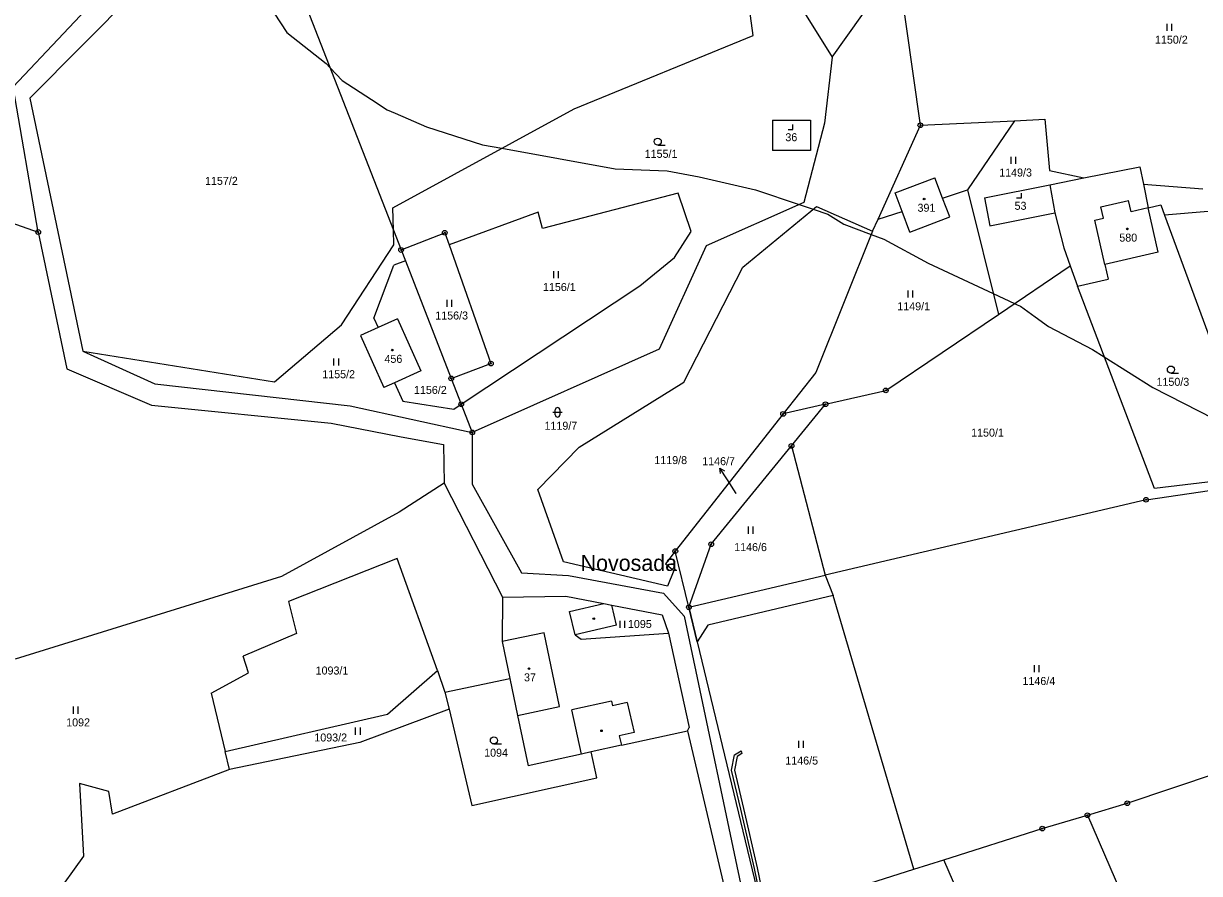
# Model space of a CAD drawing. Extents: x -439246 to -433691, y -1130252 to -1121148.
# Drawn here: x -438261.6 to -438011.8, y -1123663.3 to -1123482.7 of the extents above; entities that cross this region are included whole.
import ezdxf

# ---------------------------------------------------------------- set-up
doc = ezdxf.new("R2010")
doc.units = 0
for name, color, linetype in [('Vrstva 1', 7, 'Continuous'), ('Vrstva 16', 7, 'Continuous'), ('Vrstva 18', 7, 'Continuous'), ('Vrstva 19', 7, 'Continuous'), ('Vrstva 24', 7, 'Continuous'), ('Vrstva 25', 7, 'Continuous'), ('Vrstva 3', 7, 'Continuous'), ('Vrstva 30', 7, 'Continuous'), ('Vrstva 37', 7, 'Continuous'), ('Vrstva 4', 7, 'Continuous'), ('Vrstva 52', 7, 'Continuous'), ('Vrstva 62', 7, 'Continuous')]:
    doc.layers.add(name, color=color, linetype=linetype)

msp = doc.modelspace()

# ---------------------------------------------------------------- linework, layer by layer
at = {"layer": 'Vrstva 1'}
for p, q in [((-438023.75, -1123516.88), (-438011.16, -1123517.82)), ((-438009.98, -1123522.62), (-438019.24, -1123523.41)), ((-438091.26, -1123563.61), (-438078.47, -1123560.67)), ((-438091.26, -1123563.61), (-438100.25, -1123565.67)), ((-438098.48, -1123572.45), (-438091.26, -1123563.61)), ((-438120.28, -1123606.72), (-438091.32, -1123599.91)), ((-438089.62, -1123604.25), (-438116.28, -1123610.51)), ((-438072.52, -1123662.39), (-438089.62, -1123604.25)), ((-438116.28, -1123610.51), (-438118.5, -1123614.1)), ((-438104.43, -1123672.49), (-438072.52, -1123662.39)), ((-438072.52, -1123662.39), (-438066.16, -1123660.38))]:
    msp.add_line(p, q, dxfattribs=at)
for points in [[(-438106.64, -1123485.23), (-438113.81, -1123431.93)], [(-438206.8, -1123465.62), (-438183.03, -1123526.6)], [(-438103.03, -1123468.71), (-438089.87, -1123489.86)], [(-438089.87, -1123489.86), (-438077.24, -1123472.06)], [(-438071.12, -1123504.34), (-438075.63, -1123472.29)], [(-438263.78, -1123496.2), (-438242.36, -1123473.42)], [(-438237.94, -1123476.04), (-438260.21, -1123498.55)], [(-438144.62, -1123500.82), (-438106.64, -1123485.23)], [(-438089.87, -1123489.86), (-438091.5, -1123503.89)], [(-438258.45, -1123527.01), (-438263.78, -1123496.2)], [(-438260.21, -1123498.55), (-438248.99, -1123552.36)], [(-438183.13, -1123521.84), (-438144.62, -1123500.82)], [(-438102.52, -1123503.27), (-438094.42, -1123503.27)], [(-438102.52, -1123503.27), (-438102.52, -1123509.66)], [(-438091.5, -1123503.89), (-438095.89, -1123520.72)], [(-438094.42, -1123503.27), (-438094.42, -1123509.66)], [(-438080.11, -1123524.29), (-438071.12, -1123504.34)], [(-438071.12, -1123504.34), (-438051.14, -1123503.36)], [(-438051.14, -1123503.36), (-438061.1, -1123518.07)], [(-438051.14, -1123503.36), (-438044.71, -1123503.04)], [(-438044.71, -1123503.04), (-438043.71, -1123513.94)], [(-438094.42, -1123509.66), (-438102.52, -1123509.66)], [(-438043.71, -1123513.94), (-438036.4, -1123515.52)], [(-438036.4, -1123515.52), (-438024.49, -1123513.13)], [(-438024.49, -1123513.13), (-438023.75, -1123516.88)], [(-438285.12, -1123517.59), (-438258.45, -1123527.01)], [(-438057.46, -1123519.73), (-438043.63, -1123516.96)], [(-438043.63, -1123516.96), (-438036.4, -1123515.52)], [(-438043.63, -1123516.96), (-438042.54, -1123522.94)], [(-438023.75, -1123516.88), (-438022.76, -1123521.88)], [(-438122.56, -1123518.73), (-438151.35, -1123526.28)], [(-438119.76, -1123526.89), (-438122.56, -1123518.73)], [(-438066.38, -1123519.8), (-438061.1, -1123518.07)], [(-438064.85, -1123523.8), (-438066.38, -1123519.8)], [(-438061.1, -1123518.07), (-438054.54, -1123544.53)], [(-438057.46, -1123519.73), (-438056.37, -1123525.71)], [(-438183.03, -1123526.6), (-438183.13, -1123521.84)], [(-438095.89, -1123520.72), (-438116.59, -1123529.95)], [(-438108.81, -1123534.47), (-438093.2, -1123521.6)], [(-438093.2, -1123521.6), (-438081.26, -1123526.84)], [(-438080.11, -1123524.29), (-438075, -1123522.62)], [(-438073.32, -1123527.03), (-438075, -1123522.62)], [(-438022.76, -1123521.88), (-438020.04, -1123521.24)], [(-438020.62, -1123531.32), (-438022.76, -1123521.88)], [(-438020.04, -1123521.24), (-438019.24, -1123523.41)], [(-438152.25, -1123522.82), (-438171.21, -1123529.74)], [(-438151.35, -1123526.28), (-438152.25, -1123522.82)], [(-438081.26, -1123526.84), (-438080.11, -1123524.29)], [(-438073.32, -1123527.03), (-438064.85, -1123523.8)], [(-438056.37, -1123525.71), (-438042.54, -1123522.94)], [(-438042.54, -1123522.94), (-438040.62, -1123530.4)], [(-438019.24, -1123523.41), (-437998.91, -1123578.78)], [(-438258.45, -1123527.01), (-438252.37, -1123556.05)], [(-438182.96, -1123529.75), (-438183.03, -1123526.6)], [(-438183.03, -1123526.6), (-438181.38, -1123530.83)], [(-438181.38, -1123530.83), (-438172.12, -1123527.16)], [(-438172.12, -1123527.16), (-438171.21, -1123529.74)], [(-438123.35, -1123532.43), (-438119.76, -1123526.89)], [(-438081.26, -1123526.84), (-438093.3, -1123556.83)], [(-438194.05, -1123546.73), (-438182.96, -1123529.75)], [(-438171.21, -1123529.74), (-438162.31, -1123554.96)], [(-438116.59, -1123529.95), (-438126.59, -1123551.88)], [(-438181.38, -1123530.83), (-438180.48, -1123533.13)], [(-438130.67, -1123538.46), (-438123.35, -1123532.43)], [(-438040.62, -1123530.4), (-438039.27, -1123534.23)], [(-438020.62, -1123531.32), (-438031.93, -1123533.89)], [(-438187.18, -1123545.29), (-438182.94, -1123534.02)], [(-438180.48, -1123533.13), (-438182.94, -1123534.02)], [(-438180.48, -1123533.13), (-438170.74, -1123558.13)], [(-438121.32, -1123558.91), (-438108.81, -1123534.47)], [(-438054.54, -1123544.53), (-438039.27, -1123534.23)], [(-438039.27, -1123534.23), (-438037.75, -1123538.54)], [(-438031.93, -1123533.89), (-438031.21, -1123537.05)], [(-438037.75, -1123538.54), (-438031.21, -1123537.05)], [(-438168.6, -1123563.61), (-438130.67, -1123538.46)], [(-438021.41, -1123581.48), (-438037.75, -1123538.54)], [(-438078.47, -1123560.67), (-438054.54, -1123544.53)], [(-438208.24, -1123558.84), (-438194.05, -1123546.73)], [(-438186.28, -1123547.31), (-438190.04, -1123548.99)], [(-438187.18, -1123545.29), (-438186.28, -1123547.31)], [(-438182.14, -1123545.45), (-438186.28, -1123547.31)], [(-438182.14, -1123545.45), (-438177.18, -1123556.52)], [(-438190.04, -1123548.99), (-438185.08, -1123560.06)], [(-438248.99, -1123552.36), (-438233.67, -1123559.25)], [(-438248.99, -1123552.36), (-438208.24, -1123558.84)], [(-438126.59, -1123551.88), (-438166.27, -1123569.59)], [(-438170.74, -1123558.13), (-438162.31, -1123554.96)], [(-438252.37, -1123556.05), (-438234.4, -1123563.81)], [(-438177.18, -1123556.52), (-438182.82, -1123559.05)], [(-438093.3, -1123556.83), (-438100.25, -1123565.67)], [(-438233.67, -1123559.25), (-438192.18, -1123563.95)], [(-438182.82, -1123559.05), (-438185.08, -1123560.06)], [(-438182.82, -1123559.05), (-438181.03, -1123562.95)], [(-438170.74, -1123558.13), (-438168.6, -1123563.61)], [(-438143.54, -1123572.73), (-438121.32, -1123558.91)], [(-438234.4, -1123563.81), (-438196.24, -1123567.62)], [(-438192.18, -1123563.95), (-438166.27, -1123569.59)], [(-438181.03, -1123562.95), (-438170.21, -1123564.68)], [(-438170.21, -1123564.68), (-438168.6, -1123563.61)], [(-438168.6, -1123563.61), (-438166.27, -1123569.59)], [(-438196.24, -1123567.62), (-438181.4, -1123570.53)], [(-438100.25, -1123565.67), (-438123.15, -1123594.81)], [(-438166.27, -1123569.59), (-438166.27, -1123580.56)], [(-438181.4, -1123570.53), (-438172.36, -1123572.17)], [(-438172.36, -1123572.17), (-438172.27, -1123580.36)], [(-438115.53, -1123593.34), (-438098.48, -1123572.45)], [(-438098.48, -1123572.45), (-438091.32, -1123599.91)], [(-438152.38, -1123581.73), (-438143.54, -1123572.73)], [(-437998.91, -1123578.78), (-438021.41, -1123581.48)], [(-438172.27, -1123580.36), (-438181.78, -1123586.51)], [(-438172.27, -1123580.36), (-438159.86, -1123604.62)], [(-438166.27, -1123580.56), (-438155.83, -1123599.4)], [(-438146.9, -1123597.09), (-438152.38, -1123581.73)], [(-438023.19, -1123583.89), (-438007.33, -1123581.56)], [(-438023.19, -1123583.89), (-438091.32, -1123599.91)], [(-438181.78, -1123586.51), (-438206.75, -1123600.23)], [(-438123.15, -1123594.81), (-438125.25, -1123597.49)], [(-438120.28, -1123606.72), (-438123.15, -1123594.81)], [(-438120.28, -1123606.72), (-438115.53, -1123593.34)], [(-438182.24, -1123596.37), (-438205.27, -1123605.53)], [(-438173.64, -1123620.18), (-438182.24, -1123596.37)], [(-438124.84, -1123602.25), (-438146.9, -1123597.09)], [(-438125.25, -1123597.49), (-438123.45, -1123598.9)], [(-438155.83, -1123599.4), (-438145.87, -1123600)], [(-438145.87, -1123600), (-438125.64, -1123603.73)], [(-438123.45, -1123598.9), (-438124.84, -1123602.25)], [(-438206.75, -1123600.23), (-438263.36, -1123617.74)], [(-438159.86, -1123604.62), (-438159.92, -1123614.01)], [(-438159.86, -1123604.62), (-438146.38, -1123604.35)], [(-438146.38, -1123604.35), (-438138.31, -1123605.93)], [(-438125.64, -1123603.73), (-438121.3, -1123608.63)], [(-438205.27, -1123605.53), (-438203.63, -1123612.33)], [(-438138.31, -1123605.93), (-438136.64, -1123606.26)], [(-438135.63, -1123610.51), (-438136.64, -1123606.26)], [(-438136.64, -1123606.26), (-438125.98, -1123608.35)], [(-438120.28, -1123606.72), (-438118.5, -1123614.1)], [(-438125.98, -1123608.35), (-438124.57, -1123612.26)], [(-438121.3, -1123608.63), (-438107.59, -1123673.51)], [(-438203.63, -1123612.33), (-438214.96, -1123617.13)], [(-438135.63, -1123610.51), (-438144.42, -1123612.6)], [(-438144.42, -1123612.6), (-438143.14, -1123613.49)], [(-438143.14, -1123613.49), (-438124.57, -1123612.26)], [(-438124.57, -1123612.26), (-438120.23, -1123632.26)], [(-438159.92, -1123614.01), (-438158.28, -1123621.87)], [(-438118.5, -1123614.1), (-438104.43, -1123672.49)], [(-438213.79, -1123620.68), (-438214.96, -1123617.13)], [(-438221.75, -1123624.99), (-438213.79, -1123620.68)], [(-438184.26, -1123629.44), (-438173.64, -1123620.18)], [(-438173.64, -1123620.18), (-438172.08, -1123624.76)], [(-438172.08, -1123624.76), (-438158.28, -1123621.87)], [(-438158.28, -1123621.87), (-438156.64, -1123629.71)], [(-438221.75, -1123624.99), (-438218.77, -1123637.37)], [(-438172.08, -1123624.76), (-438171.19, -1123628.38)], [(-438218.77, -1123637.37), (-438184.26, -1123629.44)], [(-438171.19, -1123628.38), (-438190.14, -1123635.49)], [(-438171.19, -1123628.38), (-438166.35, -1123648.86)], [(-438156.64, -1123629.71), (-438154.39, -1123640.44)], [(-438120.57, -1123632.97), (-438120.23, -1123632.26)], [(-438134.61, -1123636.07), (-438120.57, -1123632.97)], [(-438120.57, -1123632.97), (-438110.79, -1123674.54)], [(-438217.84, -1123641.24), (-438218.77, -1123637.37)], [(-438190.14, -1123635.49), (-438217.84, -1123641.24)], [(-438141.03, -1123637.49), (-438143.07, -1123637.94)], [(-438134.61, -1123636.07), (-438141.03, -1123637.49)], [(-438139.81, -1123643.01), (-438141.03, -1123637.49)], [(-438143.07, -1123637.94), (-438154.39, -1123640.44)], [(-438217.84, -1123641.24), (-438242.65, -1123650.71)], [(-438027.17, -1123648.39), (-438008.04, -1123641.93)], [(-438243.46, -1123645.9), (-438249.71, -1123644.2)], [(-438249.71, -1123644.2), (-438248.86, -1123659.59)], [(-438166.35, -1123648.86), (-438139.81, -1123643.01)], [(-438242.65, -1123650.71), (-438243.46, -1123645.9)], [(-438035.64, -1123650.92), (-438027.17, -1123648.39)], [(-438045.22, -1123653.77), (-438035.64, -1123650.92)], [(-438035.64, -1123650.92), (-438008.28, -1123714.17)], [(-438066.16, -1123660.38), (-438045.22, -1123653.77)], [(-438248.86, -1123659.59), (-438255.14, -1123668.38)], [(-438051.54, -1123694.08), (-438066.16, -1123660.38)]]:
    msp.add_lwpolyline(points, dxfattribs=at)
at = {"layer": 'Vrstva 16'}
msp.add_line((-438112.05, -1123579.7), (-438113.68, -1123577.18), dxfattribs=at)
for points in [[(-438113.56, -1123578.29), (-438113.68, -1123577.18), (-438112.72, -1123577.75)], [(-438110.21, -1123582.54), (-438112.05, -1123579.7)]]:
    msp.add_lwpolyline(points, dxfattribs=at)
at = {"layer": 'Vrstva 24'}
for centre, radius in [((-438071.12, -1123504.34), 0.5), ((-438071.12, -1123504.34), 0.1), ((-438258.45, -1123527.01), 0.5), ((-438258.45, -1123527.01), 0.1), ((-438172.12, -1123527.16), 0.5), ((-438172.12, -1123527.16), 0.1), ((-438181.38, -1123530.83), 0.5), ((-438181.38, -1123530.83), 0.1), ((-438162.31, -1123554.96), 0.5), ((-438162.31, -1123554.96), 0.1), ((-438170.74, -1123558.13), 0.5), ((-438170.74, -1123558.13), 0.1), ((-438078.47, -1123560.67), 0.5), ((-438078.47, -1123560.67), 0.1), ((-438168.6, -1123563.61), 0.5), ((-438168.6, -1123563.61), 0.1), ((-438100.25, -1123565.67), 0.5), ((-438091.26, -1123563.61), 0.5), ((-438091.26, -1123563.61), 0.1), ((-438100.25, -1123565.67), 0.1), ((-438166.27, -1123569.59), 0.5), ((-438166.27, -1123569.59), 0.1), ((-438098.48, -1123572.45), 0.5), ((-438098.48, -1123572.45), 0.1), ((-438023.19, -1123583.89), 0.5), ((-438023.19, -1123583.89), 0.1), ((-438123.15, -1123594.81), 0.5), ((-438123.15, -1123594.81), 0.1), ((-438115.53, -1123593.34), 0.5), ((-438115.53, -1123593.34), 0.1), ((-438120.28, -1123606.72), 0.5), ((-438120.28, -1123606.72), 0.1), ((-438027.17, -1123648.39), 0.5), ((-438027.17, -1123648.39), 0.1), ((-438035.64, -1123650.92), 0.5), ((-438035.64, -1123650.92), 0.1), ((-438045.22, -1123653.77), 0.5), ((-438045.22, -1123653.77), 0.1)]:
    msp.add_circle(centre, radius, dxfattribs=at)
at = {"layer": 'Vrstva 25'}
for p, q in [((-438018.73, -1123484.29), (-438018.73, -1123482.79)), ((-438017.73, -1123484.29), (-438017.73, -1123482.79)), ((-438126.88, -1123508.55), (-438125.28, -1123508.55)), ((-438051.86, -1123512.52), (-438051.86, -1123511.02)), ((-438050.86, -1123512.52), (-438050.86, -1123511.02)), ((-438148.95, -1123536.85), (-438148.95, -1123535.35)), ((-438147.95, -1123536.85), (-438147.95, -1123535.35)), ((-438073.73, -1123540.94), (-438073.73, -1123539.44)), ((-438072.73, -1123540.94), (-438072.73, -1123539.44)), ((-438171.6, -1123542.9), (-438171.6, -1123541.4)), ((-438170.6, -1123542.9), (-438170.6, -1123541.4)), ((-438195.64, -1123555.37), (-438195.64, -1123553.87)), ((-438194.64, -1123555.37), (-438194.64, -1123553.87)), ((-438017.91, -1123556.99), (-438016.31, -1123556.99)), ((-438148.65, -1123565.82), (-438148.65, -1123564.82)), ((-438147.65, -1123564.82), (-438147.65, -1123565.82)), ((-438149.15, -1123565.32), (-438147.15, -1123565.32)), ((-438107.61, -1123591.11), (-438107.61, -1123589.61)), ((-438106.61, -1123591.11), (-438106.61, -1123589.61)), ((-438134.84, -1123611.14), (-438134.84, -1123609.64)), ((-438133.84, -1123611.14), (-438133.84, -1123609.64)), ((-438046.88, -1123620.56), (-438046.88, -1123619.06)), ((-438045.88, -1123620.56), (-438045.88, -1123619.06)), ((-438250.95, -1123629.35), (-438250.95, -1123627.85)), ((-438249.95, -1123629.35), (-438249.95, -1123627.85)), ((-438191.04, -1123633.82), (-438191.04, -1123632.32)), ((-438190.04, -1123633.82), (-438190.04, -1123632.32)), ((-438096.94, -1123636.6), (-438096.94, -1123635.1)), ((-438095.94, -1123636.6), (-438095.94, -1123635.1)), ((-438161.68, -1123635.79), (-438160.08, -1123635.79))]:
    msp.add_line(p, q, dxfattribs=at)
for points in [[(-438099.17, -1123505.2), (-438098.17, -1123505.2), (-438098.17, -1123504.2)], [(-438050.67, -1123519.77), (-438049.67, -1123519.77), (-438049.67, -1123518.77)]]:
    msp.add_lwpolyline(points, dxfattribs=at)
for centre, radius in [((-438126.88, -1123507.8), 0.75), ((-438070.32, -1123520.01), 0.175), ((-438027.16, -1123526.35), 0.175), ((-438183.25, -1123552.11), 0.175), ((-438017.91, -1123556.24), 0.75), ((-438140.47, -1123609.15), 0.175), ((-438154.23, -1123619.78), 0.175), ((-438161.68, -1123635.04), 0.75), ((-438138.83, -1123632.99), 0.175)]:
    msp.add_circle(centre, radius, dxfattribs=at)
for centre, start, end in [((-438148.15, -1123564.82), 0, 180), ((-438148.15, -1123565.82), 180, 0)]:
    msp.add_arc(centre, 0.5, start, end, dxfattribs=at)
at = {"layer": 'Vrstva 3'}
for points in [[(-438076.49, -1123518.71), (-438068.02, -1123515.48)], [(-438066.38, -1123519.8), (-438068.02, -1123515.48)], [(-438075, -1123522.62), (-438076.49, -1123518.71)], [(-438064.85, -1123523.8), (-438066.38, -1123519.8)], [(-438073.32, -1123527.03), (-438075, -1123522.62)], [(-438032.76, -1123521.67), (-438026.92, -1123520.34)], [(-438032.2, -1123524.1), (-438032.76, -1123521.67)], [(-438026.36, -1123522.73), (-438026.92, -1123520.34)], [(-438022.76, -1123521.88), (-438026.36, -1123522.73)], [(-438020.62, -1123531.32), (-438022.76, -1123521.88)], [(-438073.32, -1123527.03), (-438064.85, -1123523.8)], [(-438034.06, -1123524.52), (-438032.2, -1123524.1)], [(-438031.93, -1123533.89), (-438034.06, -1123524.52)], [(-438020.62, -1123531.32), (-438031.93, -1123533.89)], [(-438186.28, -1123547.31), (-438190.04, -1123548.99)], [(-438182.14, -1123545.45), (-438186.28, -1123547.31)], [(-438182.14, -1123545.45), (-438177.18, -1123556.52)], [(-438190.04, -1123548.99), (-438185.08, -1123560.06)], [(-438177.18, -1123556.52), (-438182.82, -1123559.05)], [(-438182.82, -1123559.05), (-438185.08, -1123560.06)], [(-438151.01, -1123612.14), (-438159.92, -1123614.01)], [(-438147.72, -1123627.85), (-438151.01, -1123612.14)], [(-438159.92, -1123614.01), (-438158.28, -1123621.87)], [(-438158.28, -1123621.87), (-438156.64, -1123629.71)], [(-438156.64, -1123629.71), (-438147.72, -1123627.85)]]:
    msp.add_lwpolyline(points, dxfattribs=at)
at = {"layer": 'Vrstva 30'}
for points in [[(-438120.28, -1123606.72), (-438091.32, -1123599.91)], [(-438091.32, -1123599.91), (-438089.62, -1123604.25), (-438116.28, -1123610.51), (-438118.5, -1123614.1)], [(-438118.5, -1123614.1), (-438120.28, -1123606.72)], [(-438111.2, -1123641.38), (-438110.59, -1123638.11), (-438109.17, -1123637.21), (-438109.03, -1123637.79), (-438110.05, -1123638.47), (-438110.58, -1123641.36)], [(-438109.22, -1123649.62), (-438111.2, -1123641.38)], [(-438110.58, -1123641.36), (-438108.64, -1123649.48)], [(-438106.35, -1123662.21), (-438109.22, -1123649.62)], [(-438108.64, -1123649.48), (-438105.77, -1123662.07)], [(-438105.77, -1123662.07), (-438104.17, -1123669.95), (-438104.8, -1123670.96), (-438105, -1123670.14), (-438104.81, -1123669.83), (-438106.35, -1123662.21)]]:
    msp.add_lwpolyline(points, dxfattribs=at)
at = {"layer": 'Vrstva 37'}
for centre in [(-438070.32, -1123520.01), (-438027.16, -1123526.35), (-438183.25, -1123552.11), (-438154.23, -1123619.78)]:
    msp.add_circle(centre, 0.175, dxfattribs=at)
at = {"layer": 'Vrstva 4'}
for points in [[(-438076.49, -1123518.71), (-438068.02, -1123515.48)], [(-438066.38, -1123519.8), (-438068.02, -1123515.48)], [(-438075, -1123522.62), (-438076.49, -1123518.71)], [(-438032.76, -1123521.67), (-438026.92, -1123520.34)], [(-438032.2, -1123524.1), (-438032.76, -1123521.67)], [(-438026.36, -1123522.73), (-438026.92, -1123520.34)], [(-438022.76, -1123521.88), (-438026.36, -1123522.73)], [(-438034.06, -1123524.52), (-438032.2, -1123524.1)], [(-438031.93, -1123533.89), (-438034.06, -1123524.52)], [(-438145.59, -1123607.67), (-438138.31, -1123605.93)], [(-438144.42, -1123612.6), (-438145.59, -1123607.67)], [(-438151.01, -1123612.14), (-438159.92, -1123614.01)], [(-438147.72, -1123627.85), (-438151.01, -1123612.14)], [(-438136.69, -1123626.66), (-438145.16, -1123628.53)], [(-438136.69, -1123626.66), (-438136.47, -1123627.65)], [(-438133.35, -1123626.96), (-438136.47, -1123627.65)], [(-438133.35, -1123626.96), (-438131.91, -1123633.38)], [(-438156.64, -1123629.71), (-438147.72, -1123627.85)], [(-438143.07, -1123637.94), (-438145.16, -1123628.53)], [(-438131.91, -1123633.38), (-438135.05, -1123634.07)], [(-438135.05, -1123634.07), (-438134.61, -1123636.07)]]:
    msp.add_lwpolyline(points, dxfattribs=at)
at = {"layer": 'Vrstva 52'}
for points in [[(-438218.66, -1123452.51), (-438218.57, -1123452.72), (-438217.35, -1123455.64), (-438215.77, -1123462.53), (-438215.01, -1123465.87), (-438214.42, -1123467.43), (-438211.17, -1123476.1), (-438205.63, -1123484.62), (-438197.32, -1123491.23), (-438196.46, -1123492.15), (-438193.91, -1123494.85), (-438187.69, -1123498.86), (-438184.33, -1123501.03), (-438182.65, -1123501.76), (-438176.01, -1123504.65), (-438164.08, -1123508.49)], [(-438164.08, -1123508.49), (-438160.02, -1123509.23), (-438135.96, -1123513.6), (-438124.87, -1123514.03), (-438118.06, -1123515.31), (-438106.12, -1123518.08), (-438096.87, -1123521.16), (-438093.88, -1123522.16), (-438090.78, -1123523.19), (-438087.37, -1123525.32), (-438081.53, -1123527.51), (-438078.85, -1123528.52), (-438069.48, -1123533.63), (-438055.64, -1123540.1), (-438051.11, -1123542.22), (-438050.58, -1123542.46), (-438049.87, -1123542.79), (-438046.71, -1123545.06), (-438043.91, -1123547.06), (-438034.53, -1123551.96), (-438032.05, -1123553.53), (-438021.75, -1123560.05), (-438005.55, -1123568.36)]]:
    msp.add_lwpolyline(points, dxfattribs=at)

# ---------------------------------------------------------------- texts
at = {"layer": 'Vrstva 16'}
msp.add_text('1146/7', height=1.7, dxfattribs=at).set_placement((-438117.44, -1123576.55))
at = {"layer": 'Vrstva 18'}
for s, height, p in [('1150/2', 1.7, (-438021.29, -1123486.99)), ('1155/1', 1.7, (-438129.65, -1123511.25)), ('1157/2', 1.7, (-438223.02, -1123516.99)), ('1149/3', 1.7, (-438054.37, -1123515.22)), ('1156/1', 1.7, (-438151.26, -1123539.55)), ('1149/1', 1.7, (-438076.01, -1123543.64)), ('1156/3', 1.7, (-438174.13, -1123545.6)), ('1155/2', 1.7, (-438198.13, -1123558.07)), ('1156/2', 1.7, (-438178.65, -1123561.42)), ('1150/3', 1.7, (-438020.97, -1123559.69)), ('1119/7', 1.7, (-438150.93, -1123569.02)), ('1150/1', 1.7, (-438060.33, -1123570.48)), ('1119/8', 1.7, (-438127.61, -1123576.32)), ('1146/7', 0.1, (-438110.21, -1123582.54)), ('1146/6', 1.7, (-438110.65, -1123594.81)), ('1095', 1.7, (-438133.21, -1123611.14)), ('1093/1', 1.7, (-438199.54, -1123621.03)), ('1146/4', 1.7, (-438049.43, -1123623.26)), ('1092', 1.7, (-438252.51, -1123632.05)), ('1093/2', 1.7, (-438199.81, -1123635.26)), ('1094', 1.7, (-438163.75, -1123638.49)), ('1146/5', 1.7, (-438099.79, -1123640.16))]:
    msp.add_text(s, height=height, dxfattribs=at).set_placement(p)
at = {"layer": 'Vrstva 19'}
for s, p in [('36', (-438099.78, -1123507.72)), ('391', (-438071.72, -1123522.71)), ('53', (-438051.11, -1123522.29)), ('580', (-438028.86, -1123529.05)), ('456', (-438184.92, -1123554.81)), ('37', (-438155.28, -1123622.48))]:
    msp.add_text(s, height=1.7, dxfattribs=at).set_placement(p)
at = {"layer": 'Vrstva 62'}
msp.add_text('Novosada', height=3.4, dxfattribs=at).set_placement((-438143.26, -1123599.02))

doc.saveas('drawing.dxf')
